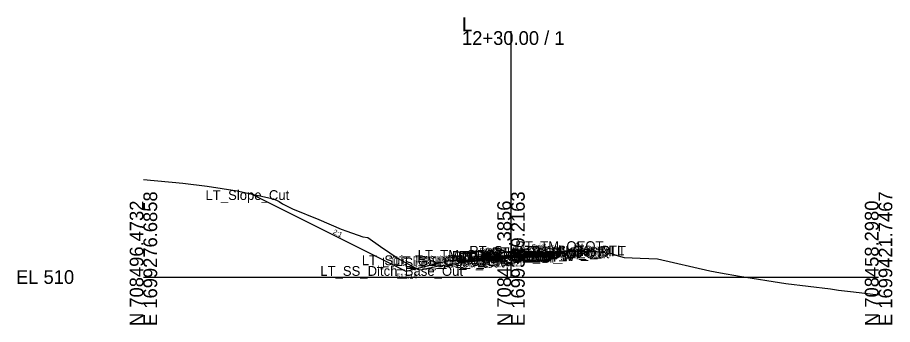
# Model space of a CAD drawing. Extents: x -63 to 1153, y -24 to 9522.
# Drawn here: x -25.7 to 152.8, y 1990.3 to 2053 of the extents above; entities that cross this region are included whole.
import ezdxf

# ---------------------------------------------------------------- set-up
doc = ezdxf.new("R2010")
doc.units = 0
for name, color, linetype in [('Default', 7, 'Continuous'), ('Exist Cross Section Cell', 7, 'Continuous'), ('Exist XS Center Line Elevation Label', 7, 'Continuous'), ('Exist XS Ground Line', 7, 'Continuous'), ('Prop CMT DNC', 7, 'Continuous'), ('Prop CMT Pvmt Course 1', 7, 'Continuous'), ('Prop CMT Pvmt Course 2', 7, 'Continuous'), ('Prop CMT Pvmt Surface', 7, 'Continuous'), ('Prop CMT Pvmt Surface Overlay', 7, 'Continuous'), ('Prop CMT Pvmt Surface Shoulder', 7, 'Continuous'), ('Prop CMT Shld Paved Course 1', 7, 'Continuous'), ('Prop CMT Shld Paved Course 2', 7, 'Continuous'), ('Prop CMT Slope Grass', 7, 'Continuous'), ('Prop CMT Subgrade Earthwork', 7, 'Continuous'), ('Prop XS Ditch Standard Text', 7, 'Continuous'), ('Prop XS Earthwork Shape', 7, 'Continuous'), ('Prop XS EOT Tick Mark', 7, 'Continuous'), ('Prop XS SE Text', 7, 'Continuous'), ('Prop XS Side Slope Text', 7, 'Continuous')]:
    doc.layers.add(name, color=color, linetype=linetype)

msp = doc.modelspace()

# ---------------------------------------------------------------- linework, layer by layer
at = {"layer": 'Exist Cross Section Cell'}
for p, q in [((75, 2000), (75, 2050.19)), ((0, 2000), (75, 2000)), ((75, 2000), (150, 2000))]:
    msp.add_line(p, q, dxfattribs=at)
at = {"layer": 'Exist XS Ground Line'}
msp.add_lwpolyline([(0, 2019.91), (8.05, 2019.17), (13.02, 2018.54), (19.15, 2017.59), (26.51, 2015.95), (27.69, 2015.39), (28.39, 2014.97), (30.43, 2013.89), (35.8, 2011.72), (40.34, 2009.79), (41.48, 2009.35), (44.8, 2008.22), (45.8, 2008.05), (48.4, 2006.21), (52.21, 2003.65), (55.74, 2001.74), (56.27, 2001.44), (56.79, 2001.52), (59.96, 2002.21), (64.68, 2002.91), (65.69, 2003.05), (72.7, 2003.93), (75, 2004.21), (75.49, 2004.27), (78.16, 2004.52), (85.6, 2005.21), (90.28, 2005.19), (92.59, 2005.21), (94.65, 2004.94), (95.54, 2004.8), (96.39, 2004.49), (98.09, 2004), (101.37, 2003.87), (104.89, 2003.71), (115.6, 2001.25), (117.76, 2000.89), (121.63, 2000.21), (131.1, 1998.65), (140.22, 1997.56), (141.79, 1997.34), (144.86, 1997.01), (150, 1996.35)], dxfattribs=at)
at = {"layer": 'Prop CMT Pvmt Course 1'}
for points in [[(75, 2004.41), (85, 2005.31)], [(85, 2005.06), (75, 2004.16)], [(85, 2005.31), (85, 2005.06)], [(75, 2004.41), (65, 2003.51)], [(65, 2003.26), (75, 2004.16)], [(65, 2003.51), (65, 2003.26)], [(75, 2004.29), (75, 2004.41)], [(75, 2004.29), (75, 2004.41)], [(75, 2004.16), (75, 2004.29), (75, 2004.29)], [(75, 2004.16), (75, 2004.29), (75, 2004.29)]]:
    msp.add_lwpolyline(points, dxfattribs=at)
at = {"layer": 'Prop CMT Pvmt Course 2'}
for points in [[(75, 2004.16), (85, 2005.06)], [(85, 2005.06), (85, 2004.81)], [(75, 2004.16), (65, 2003.26)], [(65, 2003.01), (75, 2003.91)], [(65, 2003.26), (65, 2003.01)], [(85, 2004.81), (75, 2003.91)], [(75, 2003.91), (75, 2004.16)], [(75, 2003.91), (75, 2004.16)]]:
    msp.add_lwpolyline(points, dxfattribs=at)
at = {"layer": 'Prop CMT Pvmt Surface'}
for points in [[(75, 2004.41), (85, 2005.31)], [(75, 2004.41), (65, 2003.51)]]:
    msp.add_lwpolyline(points, dxfattribs=at)
at = {"layer": 'Prop CMT Pvmt Surface Overlay'}
for points in [[(75, 2004.41), (85, 2005.31)], [(75, 2004.41), (65, 2003.51)]]:
    msp.add_lwpolyline(points, dxfattribs=at)
at = {"layer": 'Prop CMT Pvmt Surface Shoulder'}
for points in [[(85, 2005.31), (85.01, 2005.31)], [(65, 2003.51), (64.99, 2003.51)]]:
    msp.add_lwpolyline(points, dxfattribs=at)
at = {"layer": 'Prop CMT Shld Paved Course 1'}
for points in [[(85, 2005.31), (85.01, 2005.31), (85.24, 2005.08)], [(85, 2005.06), (85, 2005.31)], [(85.24, 2005.08), (85, 2005.06)], [(65, 2003.51), (64.99, 2003.51), (64.72, 2003.23)], [(64.72, 2003.23), (65, 2003.26)], [(65, 2003.26), (65, 2003.51)]]:
    msp.add_lwpolyline(points, dxfattribs=at)
at = {"layer": 'Prop CMT Shld Paved Course 2'}
for points in [[(85, 2005.06), (85.24, 2005.08)], [(85, 2004.81), (85, 2005.06)], [(85.24, 2005.08), (85.24, 2005.08)], [(85.24, 2005.08), (85.47, 2004.85)], [(64.72, 2003.23), (64.44, 2002.96)], [(65, 2003.26), (64.72, 2003.23)], [(64.72, 2003.23), (64.72, 2003.23)], [(65, 2003.01), (65, 2003.26)], [(85.47, 2004.85), (85, 2004.81)], [(64.44, 2002.96), (65, 2003.01)]]:
    msp.add_lwpolyline(points, dxfattribs=at)
at = {"layer": 'Prop CMT Slope Grass'}
for p, q in [((53.6, 2001.14), (21.94, 2016.97)), ((62, 2003.24), (53.6, 2001.14))]:
    msp.add_line(p, q, dxfattribs=at)
for points in [[(85.01, 2005.31), (88, 2005.4)], [(88, 2005.4), (88.81, 2005.2)], [(64.99, 2003.51), (62, 2003.24)]]:
    msp.add_lwpolyline(points, dxfattribs=at)
at = {"layer": 'Prop CMT Subgrade Earthwork'}
for points in [[(85.47, 2004.85), (85.96, 2005.34)], [(64.44, 2002.96), (63.98, 2003.42)], [(75, 2003.91), (65, 2003.01)], [(75, 2003.91), (85, 2004.81)], [(85, 2004.81), (85.47, 2004.85)], [(65, 2003.01), (64.44, 2002.96)]]:
    msp.add_lwpolyline(points, dxfattribs=at)
at = {"layer": 'Prop XS Earthwork Shape'}
for points in [[(44.8, 2008.22), (45.8, 2008.05), (48.4, 2006.21), (52.21, 2003.65), (55.74, 2001.74), (55.82, 2001.7), (53.6, 2001.14), (21.94, 2016.97), (26.51, 2015.95), (27.69, 2015.39), (28.39, 2014.97), (30.43, 2013.89), (35.8, 2011.72), (40.34, 2009.79), (41.48, 2009.35)], [(66.2, 2003.12), (72.7, 2003.93), (75, 2004.21), (75.49, 2004.27), (78.16, 2004.52), (85.6, 2005.21), (85.82, 2005.21), (85.47, 2004.85), (85, 2004.81), (75, 2003.91)], [(85.96, 2005.34), (88, 2005.4), (88.81, 2005.2), (85.82, 2005.21)], [(64.68, 2002.91), (65.69, 2003.05), (66.2, 2003.12), (65, 2003.01), (64.44, 2002.96), (63.98, 2003.42), (62, 2003.24), (55.82, 2001.7), (56.27, 2001.44), (56.79, 2001.52), (59.96, 2002.21)]]:
    msp.add_lwpolyline(points, close=True, dxfattribs=at)
at = {"layer": 'Prop XS EOT Tick Mark'}
for points in [[(85, 2005.31), (85, 2006.31)], [(65, 2003.51), (65, 2004.51)]]:
    msp.add_lwpolyline(points, dxfattribs=at)

# ---------------------------------------------------------------- texts
at = {"layer": 'Default'}
msp.add_text('-', height=0.0001, dxfattribs=at).set_placement((0, 2000))
at = {"layer": 'Exist Cross Section Cell'}
for s, p in [('L', (65, 2050.19)), ('12+30.00 / 1', (65, 2047.39)), ('EL 510', (-26, 1998.6))]:
    msp.add_text(s, height=2.8, dxfattribs=at).set_placement(p)
for s, p in [('E 1699276.6858', (2.8, 1990)), ('E 1699349.2163', (77.8, 1990)), ('E 1699421.7467', (152.8, 1990)), ('N 708496.4732', (0, 1990)), ('N 708477.3856', (75, 1990)), ('N 708458.2980', (150, 1990))]:
    msp.add_text(s, height=2.8, rotation=90, dxfattribs=at).set_placement(p)
at = {"layer": 'Exist XS Center Line Elevation Label'}
msp.add_text('514.21', height=1, dxfattribs=at).set_placement((73.16, 2002.19))
at = {"layer": 'Prop CMT DNC'}
for s, p in [('LT_Slope_Cut', (12.66, 2015.73)), ('RT_TM_OEOT', (75.9, 2005.31)), ('LT_TM_OEOT', (55.94, 2003.51)), ('RT_PV1_OEEOP_W', (62.94, 2003.29)), ('LT_PV1_OEEOP_W', (62.98, 2003.29)), ('RT_Sub_OEEOP', (64.17, 2002.91)), ('LT_Sub_OEEOP', (64.21, 2002.91)), ('RT_PV2_OEEOP', (64.26, 2003.16)), ('LT_PV2_OEEOP', (64.31, 2003.16)), ('RT_Sub_Trench_Out_DLT', (66.48, 2004.34)), ('PV1_PGL_W', (67.58, 2003.29)), ('PV1_PGL', (69.47, 2003.41)), ('RT_Sub_Trench_Out', (69.63, 2003.85)), ('RT_PS2_Shelf_Out', (71.18, 2004.08)), ('RT_Sub_OEOT', (75.03, 2003.81)), ('RT_PV2_OEOT', (75.13, 2004.06)), ('RT_PS2_OEOP', (75.43, 2004.08)), ('RT_PV1_OEOT', (75.69, 2004.31)), ('RT_PS1_OEOP', (75.77, 2004.31)), ('RT_GS_OS_CTL', (77.32, 2004.4)), ('RT_Slope_Fill', (79.28, 2004.2)), ('LT_Sub_Trench_Out_DLT', (44.55, 2002.42)), ('LT_Sub_Trench_Out', (48.65, 2001.96)), ('LT_PS2_Shelf_Out', (50.7, 2002.23)), ('LT_GS_OS_CTL', (51.37, 2002.24)), ('LT_PS2_OEOP', (54.95, 2002.23)), ('LT_Sub_OEOT', (55.08, 2002.01)), ('LT_PV2_OEOT', (55.17, 2002.26)), ('LT_PV1_OEOT', (55.74, 2002.51)), ('LT_PS1_OEOP', (55.79, 2002.51)), ('LT_SS_Ditch_Base_Out', (36.08, 2000.24))]:
    msp.add_text(s, height=2, dxfattribs=at).set_placement(p)
at = {"layer": 'Prop XS Ditch Standard Text'}
msp.add_text('511.14', height=1, dxfattribs=at).set_placement((51.61, 1999.67))
at = {"layer": 'Prop XS SE Text'}
for p in [(79.23, 2005.61), (68.65, 2004.84)]:
    msp.add_text('Exist', height=1, rotation=5.1428, dxfattribs=at).set_placement(p)
at = {"layer": 'Prop XS Side Slope Text'}
for s, rotation, p in [('2:1', 333.435, (38.57, 2008.91)), ('4:1', 345.9638, (87.82, 2006.22)), ('4:1', 14.0363, (57.05, 2002.78))]:
    msp.add_text(s, height=1, rotation=rotation, dxfattribs=at).set_placement(p)

doc.saveas('drawing.dxf')
